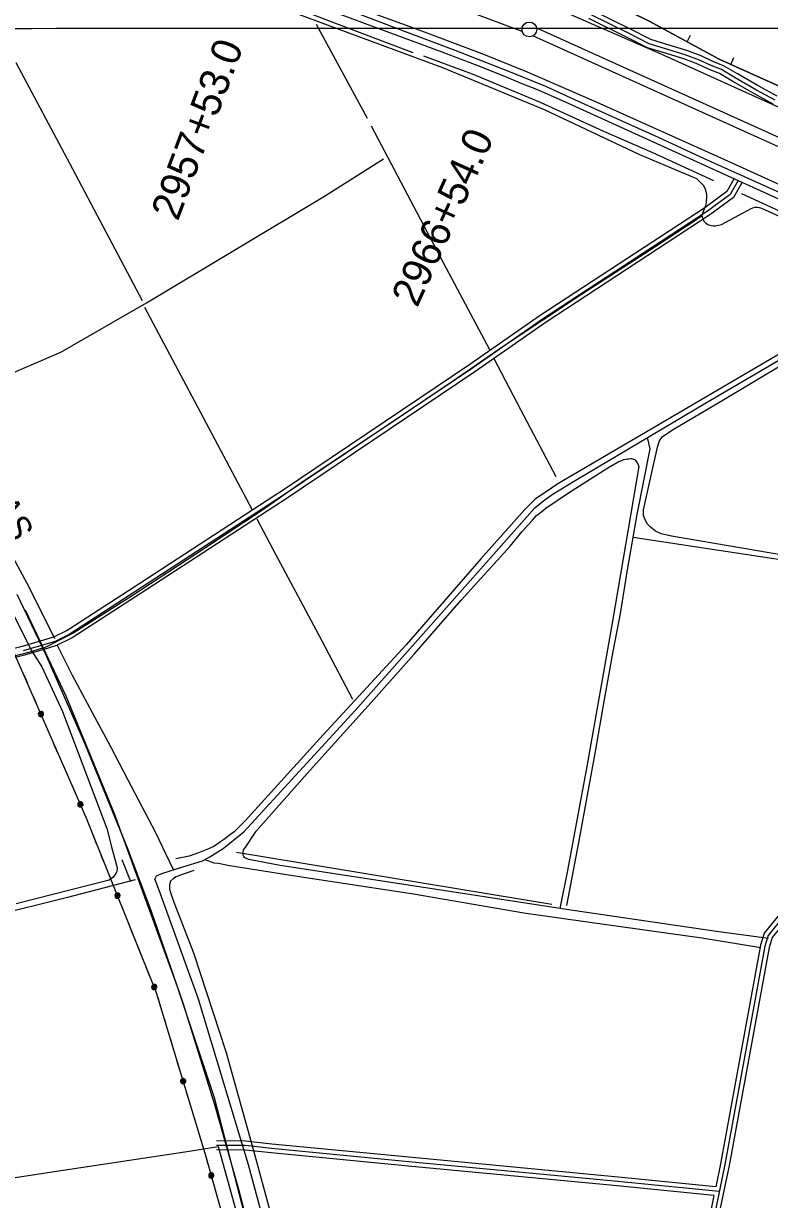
# Model space of a CAD drawing. Extents: x 3279314 to 3317160, y 734079 to 759431.
# Drawn here: x 3287854 to 3290383, y 747608 to 751596 of the extents above; entities that cross this region are included whole.
import ezdxf

# ---------------------------------------------------------------- set-up
doc = ezdxf.new("R2010")
doc.units = 0
for name, color, linetype in [('V-BORW-LINE', 7, 'Continuous'), ('V-DTCH-CNTR', 7, 'Continuous'), ('V-GRID-MAJR', 7, 'Continuous'), ('V-LEVE-TOET', 7, 'Continuous'), ('V-RAIL-IDEN', 7, 'Continuous'), ('V-RAIL-TRAK', 7, 'Continuous'), ('V-ROAD-CNTR', 7, 'Continuous'), ('V-SURV-IDEN', 7, 'Continuous'), ('V-SURV-LINE', 7, 'Continuous'), ('V-TOPO-SHOR', 7, 'Continuous'), ('V-UTIL-LINE', 7, 'Continuous')]:
    doc.layers.add(name, color=color, linetype=linetype)

msp = doc.modelspace()

# ---------------------------------------------------------------- linework, layer by layer
at = {"layer": 'V-BORW-LINE'}
for p, q in [((3290103.6, 751534.6), (3290115.5, 751556.6)), ((3290251.4, 751457.9), (3290261.6, 751480.7))]:
    msp.add_line(p, q, dxfattribs=at)
for points in [[(3292476.4, 750599.1), (3292188.6, 750640), (3291942.7, 750724.6), (3291713.9, 750817.6), (3291454.1, 750951.1), (3291413.2, 750974.1), (3291247.6, 751022.2), (3290989.6, 751144.6), (3290648.7, 751279.3), (3290212.2, 751475.5), (3289975.1, 751604.5), (3289624.4, 751777.4), (3289474.8, 751809.2), (3289073.7, 751958.5), (3288634.1, 752099.5), (3288076.2, 752324.8), (3287513.5, 752526.9)], [(3287513.5, 752526.9), (3288076.2, 752324.8), (3288634.1, 752099.5), (3289073.7, 751958.5), (3289474.8, 751809.2), (3289624.4, 751777.4), (3289975.1, 751604.5), (3290212.2, 751475.5), (3290648.7, 751279.3), (3290989.6, 751144.6), (3291247.6, 751022.2), (3291413.2, 750974.1), (3291454.1, 750951.1), (3291713.9, 750817.6), (3291942.7, 750724.6), (3292188.6, 750640), (3292476.4, 750599.1)]]:
    msp.add_lwpolyline(points, dxfattribs=at)
at = {"layer": 'V-DTCH-CNTR'}
msp.add_line((3289698, 748724.5), (3289671.7, 748595.2), dxfattribs=at)
for points in [[(3290154, 750943.7), (3290160.3, 750962.4), (3290166.7, 750979.1), (3290168.8, 750988.2), (3290169.6, 750996.3), (3290170.4, 751005.8), (3290170.3, 751016.5), (3290167.2, 751031.1), (3290163.8, 751039.3), (3290159, 751047), (3290146.5, 751059.8), (3290136.1, 751070.1), (3289942.8, 751151.1), (3289620.2, 751303.6), (3289274.9, 751445.7), (3288893.9, 751588), (3288506.9, 751731.6), (3288330.5, 751781.8), (3288027, 751904.3), (3287616.7, 752073.5), (3287489.3, 752119.3), (3287333.2, 751987)], [(3287499.4, 750282.6), (3287583.1, 750310.9), (3287980.9, 750482.2), (3288270.6, 750649.1), (3288874.3, 751011), (3289074.7, 751137.4)], [(3287648.4, 749407.1), (3287876.7, 749466), (3287911.8, 749476.5), (3287919.3, 749478), (3287935.6, 749485.1), (3287968.5, 749501.3), (3288021.1, 749528.5), (3288222.4, 749656.9), (3288471.4, 749819.2), (3288664.5, 749947.6), (3288798.3, 750042.4), (3289075.6, 750226.2), (3289311.6, 750386.1), (3289479.5, 750502), (3289745.9, 750679.1), (3289997.7, 750840.8), (3290154, 750943.7), (3290160, 750925.7), (3290165.5, 750921), (3290169.6, 750917.7), (3290173.8, 750915.1), (3290180.5, 750912.3), (3290185.7, 750911.1), (3290192.1, 750910.6), (3290200.1, 750910.1), (3290210.5, 750912.5), (3290220, 750915.1), (3290308.9, 750961.9), (3290321, 750968.6), (3290326.4, 750971.2), (3290334.7, 750973.6), (3290341.9, 750973.7), (3290348.1, 750972.7), (3290355.6, 750970.1), (3290678.8, 750823.5)], [(3290678.6, 749756.6), (3290678.5, 749755), (3290527.8, 749775.9), (3290051.1, 749858.3), (3290015.6, 749866.2), (3289996.1, 749875), (3289979.8, 749888.5), (3289969.7, 749898.7), (3289961.3, 749913), (3289956.3, 749927.5), (3289956, 749947.3), (3290003.5, 750159.8), (3290010.2, 750181), (3290020.6, 750195.4), (3290060.2, 750221.3), (3290217.1, 750314.6), (3290435.5, 750446.1), (3290652, 750568.7), (3290847, 750672.8), (3290927.7, 750717.2)], [(3290598.5, 750582.1), (3290107.6, 750294.2), (3289664.9, 750034.8), (3289622.4, 750005.9), (3289595.9, 749989.2), (3289588.9, 749983), (3289579.9, 749974.2), (3289573.2, 749967.7), (3289567.1, 749961.7), (3289560.1, 749954.7), (3289553.7, 749948.2), (3289404, 749780.8), (3289151.6, 749489.8), (3288869.8, 749184.5), (3288605, 748892.7), (3288568.2, 748855.6), (3288551.5, 748842.8), (3288541, 748835.3), (3288531.4, 748827.7), (3288522.2, 748821), (3288514.2, 748815.2), (3288499.3, 748805.3), (3288480.5, 748797), (3288447.5, 748784.1), (3288416, 748772.9), (3288369.8, 748763.6)], [(3287548.6, 750126.7), (3287881.7, 749467.5), (3287915.9, 749414.7), (3287985.9, 749262.7), (3288136.1, 748866.7), (3288153.1, 748799.3)], [(3290379.9, 748493.2), (3290203.5, 748516.9), (3289717.4, 748588.1), (3289209.9, 748666.3), (3288724.3, 748741.3), (3288617.6, 748761.3), (3288606.3, 748765.3), (3288603.3, 748767.7), (3288600.6, 748771.8), (3288598.6, 748776.4), (3288598.3, 748785.3), (3288600.2, 748793.7), (3288605.3, 748801.3), (3288642.3, 748857.2), (3288815.1, 749053.4), (3289032.6, 749293.3), (3289178.3, 749457.7), (3289337.7, 749640.6), (3289503.9, 749824.3), (3289543.9, 749873.4), (3289565.7, 749897.6), (3289579.1, 749912.6), (3289592.9, 749927.8), (3289610.6, 749941.4), (3289624.4, 749952.6), (3289702, 750005.2), (3289835.1, 750089.4), (3289869.9, 750109.4), (3289889.3, 750117.3), (3289896.1, 750118.7), (3289901.5, 750119.8), (3289906.6, 750120.4), (3289913.1, 750121.5), (3289914.7, 750121.5), (3289921.5, 750119.4), (3289924.8, 750118), (3289927.7, 750115.1), (3289935.4, 750105.1), (3289939.8, 750094), (3289850.3, 749569.2), (3289763.2, 749077.1), (3289698, 748724.5)], [(3288153.1, 748799.3), (3288165.1, 748759.4), (3288170.3, 748738.1), (3288171.5, 748731.6), (3288170.7, 748720.4), (3288167.9, 748715.9), (3288163.7, 748708.3), (3288156.4, 748700.6), (3288144.4, 748690.7), (3287829.2, 748610.7)], [(3288431.2, 748724.1), (3288382.5, 748706.8), (3288371.4, 748702.3), (3288362.7, 748697.4), (3288352.6, 748687.3), (3288348.3, 748675.9), (3288349.2, 748661.2), (3288352.1, 748649.5), (3288363.6, 748616.5), (3288430.7, 748445.3), (3288539.4, 748110.1), (3288633.9, 747774.2), (3288692.2, 747557.5), (3288802.7, 747075.2), (3288882.4, 746672.9)], [(3288515, 747786.8), (3288401, 747768.7), (3287988.8, 747706.9), (3287447.4, 747624.1), (3287015.1, 747549.4), (3286693, 747498.1), (3286342, 747449.4)], [(3289082.1, 744805.7), (3289048.6, 744993.3), (3288999.4, 745247), (3288923.3, 745613.3), (3288866, 745960.9), (3288836.1, 746160), (3288790.4, 746400.4), (3288750.1, 746614.7), (3288746.9, 746638.5), (3288748.4, 746652.1), (3288753.1, 746664.1), (3288755.4, 746673.8), (3288755.8, 746684.5), (3288724.6, 746890.6), (3288671.5, 747153.9), (3288589.1, 747517.4), (3288515, 747786.8)]]:
    msp.add_lwpolyline(points, dxfattribs=at)
at = {"layer": 'V-GRID-MAJR'}
msp.add_spline([(3283456.1, 751579.5), (3286078.9, 751579.8), (3291324.4, 751580.9), (3296570, 751582.8), (3301815.6, 751585.5), (3307061.1, 751589), (3312306.7, 751593.2), (3314929.4, 751595.5)], degree=3, dxfattribs=at)
at = {"layer": 'V-LEVE-TOET'}
for points in [[(3291978.2, 750613.6), (3291945.9, 750627.3), (3291840.3, 750672.2), (3291730.1, 750720.4), (3291692.3, 750737.9), (3291590.5, 750778.4), (3291498.8, 750821.8), (3291451.5, 750843.7), (3291366.4, 750882.6), (3291320.2, 750909), (3291256.7, 750937), (3290935.8, 751073.4), (3290635.4, 751213.7), (3290337.3, 751346.9), (3290015.2, 751492.2), (3289681.5, 751638), (3289309.5, 751792.4), (3288910.2, 751940), (3288557.3, 752056.2), (3288101.3, 752234.1), (3287745, 752353.6)], [(3287573.3, 752175.4), (3287997.5, 752019.6), (3288435.6, 751852.3), (3288853.7, 751699.8), (3289176.2, 751582.2), (3289408.1, 751494.7), (3289561, 751432.3), (3289797.9, 751329.9), (3290230.7, 751134.7), (3290605.6, 750964.2), (3291041.7, 750763), (3291427.2, 750585.9), (3291784.4, 750424.2), (3291895, 750375.9), (3291977.3, 750350.3), (3292032.9, 750337.9), (3292119.5, 750323.4), (3292289.4, 750301), (3292750.2, 750253.6)]]:
    msp.add_lwpolyline(points, dxfattribs=at)
at = {"layer": 'V-RAIL-TRAK'}
msp.add_lwpolyline([(3287831.7, 749661.3), (3287928.8, 749458.2), (3288062, 749153.7), (3288206, 748798.8), (3288287.1, 748585.7), (3288394.8, 748271.6), (3288501.5, 747930.4), (3288582.4, 747642.9), (3288610.2, 747538.7)], dxfattribs=at)
at = {"layer": 'V-ROAD-CNTR'}
for points in [[(3287063, 752326.8), (3287267.8, 752250.4), (3287686.3, 752095.6), (3288047.7, 751959.5), (3288483.2, 751793.2), (3289271.5, 751500.2), (3289390.3, 751454.8), (3289479, 751419.8), (3289543.5, 751393.4), (3289598.2, 751371.8), (3289712.3, 751320.1), (3290928.1, 750767.3), (3291722.6, 750405.5), (3291887, 750335.5), (3291919.9, 750322.1), (3291955.6, 750310.5), (3291986.7, 750299.9), (3292012, 750294.1), (3292042.4, 750286.9), (3292074.6, 750280.1), (3292105.6, 750274.9), (3292168.4, 750265.3), (3292338.9, 750248), (3294136.9, 750064.8)], [(3290395.8, 751323.2), (3290331.9, 751357.5), (3290258.9, 751399.4), (3290213.1, 751426.5), (3290178.9, 751440.6), (3290139.8, 751458.7), (3290092.6, 751476.1), (3290022.9, 751497.8), (3289969.8, 751513.8), (3289896.4, 751551.2), (3289770.4, 751613)], [(3290402.3, 751336.8), (3290339.2, 751370.6), (3290266.4, 751412.4), (3290219.8, 751440), (3290184.9, 751454.3), (3290145.5, 751472.5), (3290097.4, 751490.3), (3290027.3, 751512.1), (3289975.4, 751527.8), (3289903.1, 751564.6), (3289776.4, 751626.8)], [(3290402.3, 751336.8), (3290339.2, 751370.6), (3290266.4, 751412.4), (3290219.8, 751440), (3290184.9, 751454.3), (3290145.5, 751472.5), (3290097.4, 751490.3), (3290027.3, 751512.1), (3289975.4, 751527.8), (3289903.1, 751564.6), (3289776.4, 751626.8)], [(3290408.9, 751350.3), (3290346.5, 751383.7), (3290274, 751425.4), (3290226.5, 751453.4), (3290190.9, 751468.1), (3290151.3, 751486.4), (3290102.2, 751504.5), (3290031.7, 751526.5), (3289981, 751541.8), (3289909.8, 751578), (3289782.4, 751640.6)], [(3290276.3, 751063.7), (3290249.3, 751016.8), (3290172.2, 750959.6), (3289613.9, 750593.9), (3289375.5, 750428.1), (3288735.6, 749996.7), (3288009, 749524.6), (3287960.7, 749500.7), (3287852.9, 749469.2)], [(3290276.3, 751063.7), (3290249.3, 751016.8), (3290172.2, 750959.6), (3289613.9, 750593.9), (3289375.5, 750428.1), (3288735.6, 749996.7), (3288009, 749524.6), (3287960.7, 749500.7), (3287852.9, 749469.2)], [(3290289.3, 751056.2), (3290260.7, 751006.6), (3290180.7, 750947.3), (3289622.2, 750581.5), (3289384, 750415.7), (3288743.8, 749984.1), (3288702.3, 749957.1)], [(3290263.3, 751071.2), (3290237.8, 751027), (3290163.6, 750971.9), (3289605.5, 750606.4), (3289367, 750440.4), (3288727.3, 750009.2), (3288706.3, 749995.5)], [(3290928.2, 750766.3), (3290898.1, 750687.2), (3290747.7, 750119.6), (3290664.4, 749795.9), (3290651.9, 749695.9), (3290597.2, 749066.8), (3290556.8, 748871.2), (3290524.7, 748750), (3290507.8, 748697.9), (3290468.4, 748638.9), (3290365.3, 748511.3), (3290352.5, 748470.5), (3290216.7, 747729.3)], [(3290942.2, 750760.9), (3290912.4, 750682.6), (3290762.2, 750115.8), (3290679.2, 749793.1), (3290666.8, 749694.3), (3290612.1, 749064.6), (3290571.4, 748867.8), (3290539.1, 748745.7), (3290521.4, 748691.3), (3290480.5, 748630), (3290378.7, 748504.1), (3290367.1, 748466.9), (3290231.5, 747726.6)], [(3290942.2, 750760.9), (3290912.4, 750682.6), (3290762.2, 750115.8), (3290679.2, 749793.1), (3290666.8, 749694.3), (3290612.1, 749064.6), (3290571.4, 748867.8), (3290539.1, 748745.7), (3290521.4, 748691.3), (3290480.5, 748630), (3290378.7, 748504.1), (3290367.1, 748466.9), (3290231.5, 747726.6)], [(3288706.3, 749995.5), (3288248.2, 749697.8)], [(3288702.3, 749957.1), (3288271.8, 749677.4)], [(3288248.2, 749697.8), (3288011.1, 749543.8)], [(3288271.8, 749677.4), (3288018.5, 749512.9)], [(3287859.7, 749607.8), (3287996.9, 749316.5), (3288160.9, 748917.3), (3288374.4, 748331), (3288500.7, 747954.5), (3288586.6, 747621.7), (3288663.7, 747320.9), (3288760.6, 746864.5), (3288815, 746574.3)], [(3288011.1, 749543.8), (3288001.6, 749537.6), (3287955.3, 749514.8), (3287932.7, 749508.2)], [(3287932.7, 749508.2), (3287848.9, 749483.7), (3286964.6, 749263.8), (3286892.6, 749246.5)], [(3288018.5, 749512.9), (3288016.5, 749511.5), (3287966.2, 749486.7), (3287937.7, 749478.4)], [(3287937.7, 749478.4), (3287856.8, 749454.7), (3286971.7, 749234.7), (3286894.7, 749216.1)], [(3290527.7, 748673.6), (3290492.6, 748621.1), (3290392.2, 748496.9), (3290381.7, 748463.3), (3290246.3, 747723.9)], [(3290212.5, 747635), (3289868.4, 747669.2), (3289171.2, 747735.3), (3288694.5, 747781.5), (3288605.8, 747790.8), (3288507.7, 747791.9)], [(3290212.5, 747635), (3289868.4, 747669.2), (3289171.2, 747735.3), (3288694.5, 747781.5), (3288605.8, 747790.8), (3288507.7, 747791.9)], [(3290200.5, 747651.2), (3289869.9, 747684.1), (3289172.7, 747750.2), (3288696, 747796.4), (3288606.7, 747805.7), (3288507.9, 747806.9)], [(3290194.4, 747621.7), (3289867, 747654.3), (3289169.8, 747720.3), (3288693, 747766.6), (3288605, 747775.8), (3288507.6, 747776.9)], [(3290231.5, 747726.6), (3290193.7, 747544.5), (3290126, 747285.2), (3290076.1, 747105.1), (3290005.2, 746867), (3289979.5, 746768.3), (3289958.4, 746685.7), (3289928.8, 746564.7), (3289898.3, 746430), (3289878.8, 746326.4), (3289862.5, 746254.4), (3289856.4, 746187.6), (3289849, 746124.1), (3289842.3, 746036.8), (3289841.4, 745871.2), (3289839.7, 745735), (3289833.8, 745541.2), (3289822.9, 745346.4), (3289813.3, 745173), (3289803, 744892.8), (3289785.9, 744579.1), (3289787, 744475.4), (3289799.7, 744409)], [(3290231.5, 747726.6), (3290193.7, 747544.5), (3290126, 747285.2), (3290076.1, 747105.1), (3290005.2, 746867), (3289979.5, 746768.3), (3289958.4, 746685.7), (3289928.8, 746564.7), (3289898.3, 746430), (3289878.8, 746326.4), (3289862.5, 746254.4), (3289856.4, 746187.6), (3289849, 746124.1), (3289842.3, 746036.8), (3289841.4, 745871.2), (3289839.7, 745735), (3289833.8, 745541.2), (3289822.9, 745346.4), (3289813.3, 745173), (3289803, 744892.8), (3289785.9, 744579.1), (3289787, 744475.4), (3289799.7, 744409)], [(3290246.2, 747723.5), (3290208.3, 747541.1), (3290140.5, 747281.3), (3290090.6, 747101), (3290019.7, 746863), (3289994, 746764.6), (3289972.9, 746682.1), (3289943.4, 746561.3), (3289913, 746427), (3289893.5, 746323.4), (3289877.3, 746252.1), (3289871.3, 746186.1), (3289864, 746122.7), (3289857.3, 746036.2), (3289857, 745980.8)], [(3290216.8, 747729.6), (3290200.5, 747651.2)], [(3290194.4, 747621.7), (3290179.1, 747548), (3290111.6, 747289.1), (3290061.7, 747109.2), (3289990.8, 746871), (3289965, 746772.1), (3289943.8, 746689.3), (3289914.2, 746568.2), (3289883.6, 746433.1), (3289864.1, 746329.5), (3289847.6, 746256.8), (3289841.5, 746189.2), (3289834.1, 746125.6), (3289827.3, 746037.4), (3289827, 745980.8)]]:
    msp.add_lwpolyline(points, dxfattribs=at)
at = {"layer": 'V-SURV-LINE'}
for points in [[(3289544.9, 751569.2), (3288738.8, 751871.7)], [(3289593.3, 751581.7), (3292032.1, 750480)], [(3292019.8, 750452.6), (3289580.9, 751554.4)]]:
    msp.add_lwpolyline(points, dxfattribs=at)
msp.add_circle((3289568.9, 751576.3), 25, dxfattribs=at)
at = {"layer": 'V-TOPO-SHOR'}
for p, q in [((3289020.1, 751273.8), (3288847.2, 751593.6)), ((3290659.5, 749741.6), (3289920.8, 749853.3)), ((3289645.4, 748608.3), (3288576, 748785.3)), ((3288217.1, 748688.9), (3288188.2, 748759.7))]:
    msp.add_line(p, q, dxfattribs=at)
for points in [[(3287659.1, 752127), (3287864.7, 752046.8), (3288088, 751968.6), (3288312.5, 751882.3), (3288542.3, 751795.7), (3288570.9, 751785.1), (3288748.7, 751720.6), (3288948.8, 751644.6), (3289156.9, 751566), (3289310.3, 751508.8), (3289503.4, 751432.8), (3289623.4, 751384), (3289722.4, 751339.3), (3289836.6, 751286.6), (3290005.8, 751210.8), (3290164.1, 751137.1), (3290374.9, 751042.6), (3290544.9, 750966.9), (3290701, 750895.7)], [(3289175, 751497.1), (3288900.2, 751601.1), (3288609.1, 751713.5), (3288541.5, 751740.2)], [(3288256.8, 750655.9), (3288010.7, 751121.6), (3287829.1, 751463.2)], [(3290193.7, 751062.9), (3289984.8, 751158.5), (3289821.1, 751229.8), (3289606.3, 751328.4), (3289375.8, 751424.3), (3289211.2, 751485.3)], [(3289435, 750490.2), (3289278.3, 750782.7), (3289122.5, 751078.4), (3289033.2, 751248.6)], [(3290872.7, 750754.2), (3290614.4, 750870.8), (3290390.2, 750972), (3290289.6, 751019)], [(3288468.1, 748760.8), (3288485.7, 748770.1), (3288530.4, 748798.6), (3288601.2, 748855.1), (3288978.4, 749266.6), (3289412.4, 749755.6), (3289587.2, 749954.1), (3289616.5, 749977.6), (3289646.3, 749999.4), (3289724.3, 750046.5), (3290164, 750307.4), (3290731.4, 750639.6), (3290906.6, 750736.6)], [(3288630.5, 749945.7), (3288435, 750314.9), (3288265.3, 750633.3)], [(3289659.9, 750059.6), (3289540.2, 750286.4), (3289447.9, 750461.1)], [(3287959.9, 749509.8), (3287873.9, 749682.1), (3287795.5, 749829.8), (3287710.2, 749991.6), (3287645.9, 750115.5), (3287578.6, 750239.1), (3287556.1, 750287.8)], [(3289758.6, 748942.1), (3289792.6, 749127.3), (3289824.1, 749303.7), (3289853, 749466.5), (3289877.5, 749596), (3289901.3, 749743.8), (3289934.7, 749931.6), (3289978.2, 750154), (3289969.8, 750192.2)], [(3288969.9, 749303.5), (3288855, 749523.2), (3288700.2, 749812.5), (3288646.4, 749915)], [(3288362.2, 748726.3), (3288301.5, 748853.9), (3288209, 749030.4), (3288150.3, 749143.1), (3288087.5, 749258.8), (3288019.5, 749385.7), (3287969.4, 749486.9)], [(3289696.2, 748604.8), (3289736.7, 748819.3), (3289758.7, 748942.1)], [(3288616.8, 747725.5), (3288576.1, 747860.6), (3288446.7, 748287.1), (3288314.8, 748653.7), (3288301.9, 748686.4), (3288299.6, 748694.2), (3288305.1, 748706.4), (3288322.8, 748713.7), (3288393.7, 748736.3), (3288460.2, 748756.6), (3288468.1, 748760.8)], [(3288468.1, 748760.8), (3288498.7, 748749.9), (3288514.8, 748748.3), (3288547, 748742.4), (3288766.4, 748707), (3289175.7, 748644.3), (3289550.5, 748580.9), (3289773.8, 748548.3), (3290153, 748496), (3290354.1, 748463.3)], [(3288232, 748692.8), (3288003.3, 748632.6), (3287738.6, 748566.9), (3287462.5, 748495.9), (3287171.4, 748416.5), (3286884.9, 748340), (3286642, 748276.7)], [(3288845.1, 746663.7), (3288843, 746669.6), (3288841.3, 746678.5), (3288816.9, 746845.1), (3288768.8, 747100.5), (3288711.4, 747358.2), (3288674, 747511.7), (3288616.8, 747725.5)]]:
    msp.add_lwpolyline(points, dxfattribs=at)
at = {"layer": 'V-UTIL-LINE'}
for points in [[(3288738.4, 746569.3), (3288636.9, 747168.8), (3288472.7, 747753.3), (3288305, 748308.9), (3288066.2, 748903.2), (3287813.4, 749483), (3287572, 750013.5), (3287250.9, 750510.8), (3286873.5, 750937.9), (3286412.5, 751389.7), (3286105.8, 751626.1), (3285807.9, 751895.5), (3285494.3, 752160.6), (3284875.4, 752907.1), (3284538.1, 753405.9), (3283938.7, 754373.8), (3283626.5, 754851.9)], [(3287868, 749357.9), (3287854.4, 749389.1)], [(3287897.6, 749290.1), (3287884, 749321.2)], [(3287913.1, 749254.3), (3287911.6, 749251.9), (3287913.9, 749252), (3287915.3, 749254.4), (3287913.9, 749256.9), (3287910.7, 749255.7), (3287908.9, 749251.4), (3287912.1, 749248.5), (3287916.9, 749249.2), (3287918.8, 749253.4), (3287917.9, 749257.8), (3287913.6, 749260), (3287908.4, 749258.1), (3287904.9, 749250.7), (3287906.9, 749247.8), (3287909.8, 749245.9), (3287913.3, 749245.3), (3287916.7, 749246.1), (3287919.6, 749248.1), (3287921.5, 749251), (3287922.1, 749254.5), (3287921.4, 749257.9), (3287919.4, 749260.8), (3287916.4, 749262.7), (3287913, 749263.3), (3287909.5, 749262.6), (3287906.7, 749260.6), (3287904.8, 749257.6), (3287904.1, 749254.2), (3287904.9, 749250.7)], [(3287942.3, 749187.4), (3287928.7, 749218.6)], [(3287971.9, 749119.6), (3287958.3, 749150.7)], [(3288001.5, 749051.7), (3287987.9, 749082.9)], [(3288031, 748983.9), (3288017.4, 749015.1)], [(3288046.6, 748948.2), (3288045.1, 748945.7), (3288047.4, 748945.8), (3288048.8, 748948.2), (3288047.4, 748950.8), (3288044.2, 748949.5), (3288042.4, 748945.2), (3288045.5, 748942.4), (3288050.4, 748943.1), (3288052.2, 748947.2), (3288051.4, 748951.6), (3288047.1, 748953.8), (3288041.9, 748951.9), (3288038.4, 748944.6), (3288040.4, 748941.7), (3288043.3, 748939.8), (3288046.8, 748939.2), (3288050.2, 748939.9), (3288053.1, 748941.9), (3288055, 748944.9), (3288055.6, 748948.3), (3288054.9, 748951.8), (3288052.9, 748954.6), (3288049.9, 748956.5), (3288046.5, 748957.2), (3288043, 748956.4), (3288040.1, 748954.4), (3288038.2, 748951.4), (3288037.6, 748948), (3288038.4, 748944.6)], [(3288075.1, 748881), (3288066.2, 748903.2), (3288062.2, 748912.4)], [(3288102.7, 748812.3), (3288090.1, 748843.9)], [(3288130.3, 748743.6), (3288117.6, 748775.2)], [(3288157.9, 748675), (3288145.2, 748706.5)], [(3288172.4, 748638.8), (3288170.9, 748636.4), (3288173.2, 748636.4), (3288174.6, 748638.8), (3288173.3, 748641.4), (3288170, 748640.2), (3288168.1, 748636), (3288171.2, 748633), (3288176, 748633.6), (3288178, 748637.7), (3288177.3, 748642.1), (3288173.1, 748644.4), (3288167.8, 748642.7), (3288164.1, 748635.4), (3288166, 748632.5), (3288168.9, 748630.5), (3288172.3, 748629.8), (3288175.8, 748630.4), (3288178.7, 748632.4), (3288180.7, 748635.2), (3288181.4, 748638.7), (3288180.8, 748642.1), (3288178.9, 748645.1), (3288176, 748647.1), (3288172.5, 748647.8), (3288169.1, 748647.1), (3288166.1, 748645.2), (3288164.2, 748642.3), (3288163.4, 748638.9), (3288164.1, 748635.4)], [(3288199.7, 748571), (3288187, 748602.6)], [(3288227.2, 748502.4), (3288214.6, 748533.9)], [(3288254.8, 748433.7), (3288242.1, 748465.3)], [(3288282.4, 748365), (3288269.7, 748396.6)], [(3288296.9, 748328.9), (3288295.4, 748326.5), (3288297.7, 748326.5), (3288299.1, 748328.8), (3288297.8, 748331.4), (3288294.5, 748330.3), (3288292.6, 748326), (3288295.7, 748323.1), (3288300.5, 748323.7), (3288302.5, 748327.8), (3288301.8, 748332.2), (3288297.6, 748334.5), (3288292.4, 748332.7), (3288288.6, 748325.5), (3288290.5, 748322.6), (3288293.4, 748320.6), (3288296.9, 748319.9), (3288300.3, 748320.5), (3288303.2, 748322.4), (3288305.2, 748325.3), (3288305.9, 748328.8), (3288305.3, 748332.2), (3288303.4, 748335.2), (3288300.5, 748337.1), (3288297, 748337.9), (3288293.6, 748337.2), (3288290.6, 748335.3), (3288288.7, 748332.4), (3288287.9, 748329), (3288288.6, 748325.5)], [(3288319.8, 748259.6), (3288310, 748292.2)], [(3288341.2, 748188.8), (3288331.4, 748221.3)], [(3288362.6, 748117.9), (3288352.8, 748150.5)], [(3288384, 748047.1), (3288374.2, 748079.6)], [(3288395.3, 748009.7), (3288393.5, 748007.5), (3288395.8, 748007.3), (3288397.5, 748009.5), (3288396.3, 748012.2), (3288393, 748011.4), (3288390.7, 748007.3), (3288393.5, 748004.1), (3288398.4, 748004.2), (3288400.7, 748008.2), (3288400.4, 748012.6), (3288396.4, 748015.3), (3288391, 748014), (3288386.6, 748007.1), (3288388.3, 748004), (3288391, 748001.8), (3288394.4, 748000.8), (3288397.9, 748001.1), (3288401, 748002.8), (3288403.2, 748005.5), (3288404.2, 748008.8), (3288403.9, 748012.3), (3288402.2, 748015.4), (3288399.5, 748017.7), (3288396.2, 748018.7), (3288392.7, 748018.4), (3288389.6, 748016.7), (3288387.3, 748014), (3288386.3, 748010.6), (3288386.6, 748007.1)], [(3288416.4, 747939.9), (3288406.5, 747972.4)], [(3288437.7, 747869), (3288427.9, 747901.6)], [(3288459.1, 747798.2), (3288449.3, 747830.7)], [(3288480, 747727.2), (3288472.7, 747753.3), (3288470.7, 747759.9)], [(3288490.6, 747689.6), (3288488.7, 747687.4), (3288491, 747687.2), (3288492.7, 747689.4), (3288491.6, 747692.1), (3288488.3, 747691.3), (3288485.9, 747687.3), (3288488.7, 747684.1), (3288493.6, 747684.1), (3288496, 747688), (3288495.8, 747692.4), (3288491.8, 747695.2), (3288486.4, 747694), (3288481.9, 747687.2), (3288483.5, 747684.1), (3288486.2, 747681.8), (3288489.5, 747680.7), (3288493, 747681), (3288496.1, 747682.6), (3288498.4, 747685.2), (3288499.5, 747688.6), (3288499.2, 747692.1), (3288497.6, 747695.2), (3288495, 747697.5), (3288491.6, 747698.6), (3288488.1, 747698.3), (3288485, 747696.7), (3288482.7, 747694), (3288481.6, 747690.7), (3288481.9, 747687.2)], [(3288510.3, 747619.4), (3288501.1, 747652.1)]]:
    msp.add_lwpolyline(points, dxfattribs=at)

# ---------------------------------------------------------------- texts
at = {"layer": 'V-RAIL-IDEN'}
msp.add_text('TEXAS', height=83, rotation=297.7896, dxfattribs=at).set_placement((3287648.8, 750156.9))
at = {"layer": 'V-SURV-IDEN'}
for s, rotation, p in [('2957+53.0', 69.4242, (3288377.2, 750923.6)), ('2966+54.0', 65.6753, (3289188.6, 750630.2))]:
    msp.add_text(s, height=100, rotation=rotation, dxfattribs=at).set_placement(p)

doc.saveas('drawing.dxf')
